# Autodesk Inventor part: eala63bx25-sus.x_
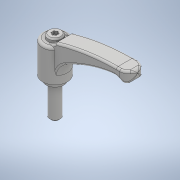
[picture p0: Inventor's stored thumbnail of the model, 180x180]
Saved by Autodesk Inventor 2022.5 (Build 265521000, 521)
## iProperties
Created: 2018-05
Part Number: eala63bx25-sus.x_
Material: 一般
Document SubType Name: Modeling
Designer: imaocorp
Density: 1 g/cm^3
Appearance: 既定
Sending System: SOLIDWORKS 2016-2016286
MC: AMD64
MC_MODEL: AMD64 Family 21 Model 2 Stepping 0, AuthenticAMD
OS: Windows_NT
FRU: Parasolid Version 28.0, build 224,  7-29-2016
FORMAT: text
GUISE: transmit
KEY: eala63bx25-sus
FILE: eala63bx25-sus.x_t
DATE: Fri May 18 11:30:31 2018
Author: imaocorp
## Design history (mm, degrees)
feature "Base1"
node "ソリッド1"
